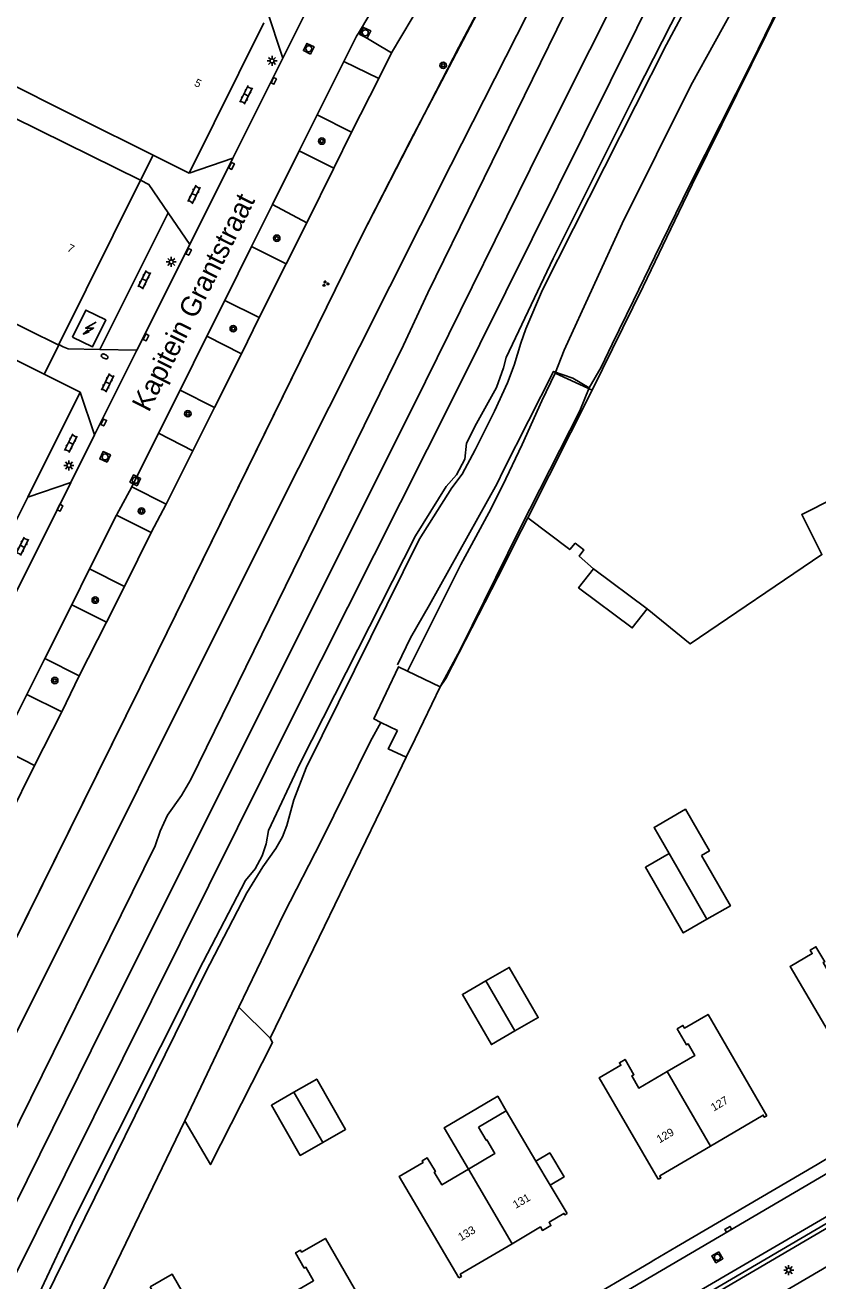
# Model space of a CAD drawing. Extents: x 135999 to 138000, y 396000 to 398501.
# Drawn here: x 136118.4 to 136217.5, y 397514.6 to 397671.5 of the extents above; entities that cross this region are included whole.
import ezdxf

# ---------------------------------------------------------------- set-up
doc = ezdxf.new("R2010")
doc.units = 0
for name, color, linetype in [('gg-afsc-hekwerk', 7, 'Continuous'), ('gg-afsc-muur', 7, 'Continuous'), ('gg-anno-huisnummerreeks BGT', 7, 'Continuous'), ('gg-anno-openbare ruimte label', 7, 'Continuous'), ('gg-aspt-spoorlijn', 7, 'Continuous'), ('gg-bbg-bijgebouw', 7, 'Continuous'), ('gg-bbg-gedigitaliseerde bebouwing', 7, 'Continuous'), ('gg-bbg-gedigitaliseerde bijgebouw', 7, 'Continuous'), ('gg-bbg-hoofdgebouw', 7, 'Continuous'), ('gg-bbg-luifel en loopbrug', 7, 'Continuous'), ('gg-bbg-overig bouwwerk', 7, 'Continuous'), ('gg-bbg-tussenscheiding', 7, 'Continuous'), ('gg-knt-verharding', 7, 'Continuous'), ('gg-knt-verharding nz', 7, 'Continuous'), ('gt-grn-bladgrens', 7, 'Continuous'), ('gt-grn-groengrens', 7, 'Continuous'), ('gt-grn-vlakafsluiter', 7, 'Continuous'), ('gt-grn-weggrens', 7, 'Continuous'), ('gt-symb-boom', 7, 'Continuous'), ('gt-symb-brandkraan', 7, 'Continuous'), ('gt-symb-groenvak', 7, 'Continuous'), ('gt-symb-klinker verharding', 7, 'Continuous'), ('gt-symb-kolk', 7, 'Continuous'), ('gt-symb-kolk center center', 7, 'Continuous'), ('gt-symb-lichtmast', 7, 'Continuous'), ('gt-symb-rioolschacht', 7, 'Continuous'), ('gt-symb-trafo symbool', 7, 'Continuous'), ('gx-grn-maaiveld', 7, 'Continuous')]:
    doc.layers.add(name, color=color, linetype=linetype)

# ---------------------------------------------------------------- blocks, each defined once
blk = doc.blocks.new('gt0-BOOM')
at = {"layer": 'gt-symb-boom'}
for radius in [0.4, 0.2]:
    blk.add_circle((0, 0), radius, dxfattribs=at)
blk = doc.blocks.new('gt0-RS')
at = {"layer": 'gt-symb-rioolschacht'}
blk.add_lwpolyline([(-0.5, -0.5), (0.5, -0.5), (0.5, 0.5), (-0.5, 0.5)], close=True, dxfattribs=at)
blk.add_circle((0, 0), 0.375, dxfattribs=at)
blk = doc.blocks.new('gt0-GRVAK')
at = {"layer": 'gt-symb-groenvak'}
for p, q in [((-0.11, 0.19), (-0.23, 0.24)), ((-0.18, 0.15), (0.09, 0.15)), ((-0.09, 0.21), (-0.16, 0.32)), ((-0.05, 0.21), (-0.05, 0.39)), ((0, 0.21), (0.06, 0.32)), ((0.02, 0.19), (0.13, 0.24)), ((0.26, -0.05), (0.2, 0.06)), ((0.3, -0.05), (0.3, 0.13)), ((0.35, -0.05), (0.41, 0.06)), ((-0.24, -0.23), (-0.36, -0.18)), ((-0.32, -0.26), (-0.05, -0.26)), ((-0.23, -0.21), (-0.29, -0.1)), ((-0.18, -0.2), (-0.18, -0.02)), ((-0.14, -0.21), (-0.07, -0.1)), ((-0.12, -0.23), (0, -0.18)), ((0.24, -0.07), (0.12, -0.02)), ((0.17, -0.11), (0.44, -0.11)), ((0.37, -0.07), (0.49, -0.02))]:
    blk.add_line(p, q, dxfattribs=at)
blk = doc.blocks.new('gt0-LMAST')
at = {"layer": 'gt-symb-lichtmast'}
for p, q in [((-0.18, 0.17), (-0.45, 0.44)), ((-0.01, 0.25), (-0.01, 0.62)), ((0.17, 0.17), (0.44, 0.44)), ((-0.26, 0), (-0.63, 0)), ((-0.18, -0.18), (-0.45, -0.45)), ((-0.01, -0.25), (-0.01, -0.63)), ((0.44, -0.45), (0.17, -0.18)), ((0.24, 0), (0.62, 0))]:
    blk.add_line(p, q, dxfattribs=at)
blk.add_circle((-0.01, 0), 0.25, dxfattribs=at)
blk = doc.blocks.new('gt0-KOLKCC')
at = {"layer": 'gt-symb-kolk center center'}
blk.add_lwpolyline([(-0.38, 0.2), (0.38, 0.2), (0.38, -0.2), (-0.38, -0.2)], close=True, dxfattribs=at)
blk = doc.blocks.new('gt0-KL1')
at = {"layer": 'gt-symb-klinker verharding'}
for p, q in [((-1.15, 0.3), (1.15, 0.3)), ((-1, -0.3), (-1, 0.3)), ((-0.5, 0.3), (-0.5, 0.45)), ((0, -0.3), (0, 0.3)), ((0.5, 0.3), (0.5, 0.45)), ((1, -0.3), (1, 0.3)), ((-1.15, -0.3), (1.15, -0.3)), ((-0.5, -0.45), (-0.5, -0.3)), ((0.5, -0.45), (0.5, -0.3))]:
    blk.add_line(p, q, dxfattribs=at)
blk = doc.blocks.new('gt0-BR')
at = {"layer": 'gt-symb-brandkraan'}
for centre, radius, start, end in [((-0.24, 0), 0.206, 107.5669, 252.4331), ((0.6, -2.66), 3, 106.892, 107.5669), ((0, -0.69), 0.938, 73.108, 106.892), ((-0.6, -2.66), 3, 72.4331, 73.108), ((0.24, 0), 0.206, 287.567, 72.4331), ((0.6, 2.66), 3, 252.4331, 253.108), ((0, 0.69), 0.938, 253.108, 286.8921), ((-0.6, 2.66), 3, 286.8921, 287.567)]:
    blk.add_arc(centre, radius, start, end, dxfattribs=at)
blk = doc.blocks.new('gt0-HSP')
at = {"layer": 'gt-symb-trafo symbool'}
for points in [[(0.77, 0.75), (-0.53, 0), (0.47, 0), (-0.83, -0.75)], [(-0.22, -0.24), (-0.83, -0.75), (-0.08, -0.48)]]:
    blk.add_lwpolyline(points, dxfattribs=at)
blk = doc.blocks.new('gt0-KOLK')
at = {"layer": 'gt-symb-kolk'}
blk.add_lwpolyline([(0, 0), (0.38, 0), (0.38, 0.4), (-0.38, 0.4), (-0.38, 0), (0, 0)], dxfattribs=at)

msp = doc.modelspace()

# ---------------------------------------------------------------- linework, layer by layer
at = {"layer": 'gg-afsc-hekwerk'}
for points in [[(136206.22, 397710.07), (136203.26, 397711.27), (136196.98, 397710.23), (136193.86, 397709.75), (136188.71, 397699.53), (136178.32, 397679.53), (136172.59, 397668.77), (136160.48, 397645.24), (136132.77, 397588.81), (136102.14, 397526.87), (136090.23, 397502.97), (136088.59, 397499.81), (136086.91, 397496.59), (136075.23, 397472.87), (136076.15, 397472.41)], [(136214.71, 397678.23), (136211.7, 397672), (136209.11, 397666.71), (136201.46, 397651.57), (136197.09, 397642.6), (136194.4, 397637.1), (136191.77, 397631.66), (136190.36, 397628.79), (136188.87, 397626.19)], [(136164.95, 397591.58), (136166.54, 397594.96), (136168.91, 397599.09), (136177.38, 397614.23), (136178.18, 397615.9), (136184.44, 397628.25), (136186.83, 397627.39), (136188.87, 397626.19)], [(136170.26, 397588.86), (136172.76, 397593.46), (136180.21, 397608.58), (136187.72, 397623.34), (136188.87, 397626.19)]]:
    msp.add_lwpolyline(points, dxfattribs=at)
at = {"layer": 'gg-afsc-muur'}
for p, q in [((136217.35, 397529.16), (136199.77, 397518.9)), ((136217.35, 397529.16), (136199.77, 397518.9)), ((136196.49, 397516.94), (136196.94, 397517.22)), ((136196.49, 397516.94), (136196.94, 397517.22))]:
    msp.add_line(p, q, dxfattribs=at)
at = {"layer": 'gg-aspt-spoorlijn'}
for points in [[(136075.9, 397441.46), (136078.9, 397447.5), (136110.62, 397511), (136126.65, 397543.4), (136168.42, 397626.98), (136182.98, 397656.49), (136206.97, 397704.32), (136208.88, 397708.17)], [(136081.38, 397443.76), (136105.46, 397491.91), (136152.12, 397585.65), (136171.93, 397625.02), (136194.83, 397671.15), (136212.4, 397706.41)]]:
    msp.add_lwpolyline(points, dxfattribs=at)
at = {"layer": 'gg-bbg-bijgebouw'}
msp.add_lwpolyline([(136124.34, 397632.55), (136126.81, 397631.32), (136128.49, 397634.69), (136126.01, 397635.92), (136124.34, 397632.55)], dxfattribs=at)
at = {"layer": 'gg-bbg-gedigitaliseerde bebouwing'}
for p, q in [((136125.05, 397659.93), (136071.25, 397686.71)), ((136134.4, 397655.27), (136125.05, 397659.93)), ((136132.84, 397652.13), (136123.46, 397656.75)), ((136138.89, 397653.04), (136134.4, 397655.27)), ((136175.07, 397533.84), (136178.52, 397535.88)), ((136178.52, 397535.88), (136182.23, 397529.6)), ((136182.23, 397529.6), (136184.01, 397526.59)), ((136184.01, 397526.59), (136186.11, 397523.04))]:
    msp.add_line(p, q, dxfattribs=at)
for points in [[(136123.46, 397656.75), (136096.92, 397669.84), (136086.86, 397649.26), (136103.12, 397641.19)], [(136221.4, 397541.27), (136213.99, 397553.91), (136216.74, 397555.53), (136216.49, 397555.96), (136217.21, 397556.38), (136218.31, 397554.51), (136218.1, 397554.39), (136219.06, 397552.75), (136222.49, 397554.77)], [(136198.63, 397540.78), (136202.09, 397542.79), (136201.24, 397544.25), (136201.03, 397544.13), (136199.88, 397546.12), (136200.6, 397546.54), (136200.78, 397546.22), (136203.73, 397547.92), (136211.08, 397535.24)], [(136197.49, 397527.32), (136190.13, 397540), (136192.84, 397541.57), (136192.66, 397541.88), (136193.36, 397542.29), (136194.46, 397540.38), (136194.19, 397540.23), (136195.07, 397538.72), (136198.63, 397540.78)], [(136173.8, 397528.6), (136177.1, 397530.55), (136176.1, 397532.25), (136176.03, 397532.21), (136175.07, 397533.84)], [(136172.6, 397515.03), (136165.13, 397527.67), (136168.13, 397529.44), (136168.02, 397529.63), (136168.65, 397530), (136169.66, 397528.29), (136169.53, 397528.21), (136170.46, 397526.64), (136173.8, 397528.6)], [(136163.28, 397507.24), (136155.93, 397519.94), (136152.95, 397518.22), (136152.8, 397518.48), (136152.19, 397518.14), (136153.29, 397516.23), (136153.48, 397516.34), (136154.45, 397514.65), (136151.05, 397512.69)]]:
    msp.add_lwpolyline(points, dxfattribs=at)
at = {"layer": 'gg-bbg-gedigitaliseerde bijgebouw'}
for points in [[(136198.87, 397568.02), (136196.99, 397571.29), (136200.91, 397573.55), (136203.9, 397568.35), (136202.9, 397567.77)], [(136203.6, 397559.81), (136200.63, 397558.1), (136195.9, 397566.31), (136198.87, 397568.02)], [(136203.6, 397559.81), (136206.52, 397561.49), (136202.9, 397567.77)], [(136179.61, 397545.85), (136182.51, 397547.52), (136178.9, 397553.8), (136175.98, 397552.12)], [(136179.61, 397545.85), (136176.67, 397544.15), (136173.05, 397550.43), (136175.98, 397552.12)], [(136155.62, 397531.93), (136158.45, 397533.56), (136154.84, 397539.85), (136152, 397538.21)], [(136155.62, 397531.93), (136152.78, 397530.3), (136149.17, 397536.58), (136152, 397538.21)], [(136134.04, 397513.88), (136136.78, 397515.46), (136141.07, 397508.01), (136138.32, 397506.43), (136134.04, 397513.88)]]:
    msp.add_lwpolyline(points, dxfattribs=at)
at = {"layer": 'gg-bbg-hoofdgebouw'}
for p, q in [((136148.25, 397671.8), (136138.89, 397653.04)), ((136132.84, 397652.13), (136122.64, 397631.61)), ((136122.6, 397631.52), (136111.61, 397636.98)), ((136122.64, 397631.61), (136122.6, 397631.52)), ((136120.8, 397627.91), (136125.3, 397625.66)), ((136125.3, 397625.66), (136118.75, 397612.54)), ((136118.75, 397612.54), (136117.04, 397609.12))]:
    msp.add_line(p, q, dxfattribs=at)
for points in [[(136111.61, 397636.98), (136109.84, 397633.37), (136120.8, 397627.91)], [(136211.08, 397535.24), (136210.76, 397535.08), (136210.62, 397535.34), (136204.02, 397531.47)], [(136204.02, 397531.47), (136197.69, 397527.75), (136197.82, 397527.48), (136197.49, 397527.32)], [(136186.11, 397523.04), (136185.85, 397522.87), (136185.72, 397523.05), (136183.88, 397521.96), (136184.1, 397521.55), (136183.03, 397520.94), (136182.78, 397521.37), (136179.24, 397519.28)], [(136179.24, 397519.28), (136172.77, 397515.46), (136172.91, 397515.18), (136172.6, 397515.03)]]:
    msp.add_lwpolyline(points, dxfattribs=at)
at = {"layer": 'gg-bbg-luifel en loopbrug'}
for points in [[(136178.52, 397535.88), (136177.45, 397537.69), (136170.76, 397533.74), (136173.8, 397528.6)], [(136184.01, 397526.59), (136185.74, 397527.61), (136183.96, 397530.62), (136182.23, 397529.6)]]:
    msp.add_lwpolyline(points, dxfattribs=at)
at = {"layer": 'gg-bbg-overig bouwwerk'}
for p, q in [((136170.26, 397588.86), (136166.18, 397590.82)), ((136167.12, 397582.36), (136170.26, 397588.86)), ((136162.86, 397584.41), (136164.93, 397583.41)), ((136167.12, 397582.36), (136166.02, 397580.08))]:
    msp.add_line(p, q, dxfattribs=at)
for points in [[(136166.18, 397590.82), (136165.05, 397591.36), (136161.99, 397584.83), (136162.86, 397584.41)], [(136164.93, 397583.41), (136163.77, 397581.1), (136166.02, 397580.08)]]:
    msp.add_lwpolyline(points, dxfattribs=at)
at = {"layer": 'gg-bbg-tussenscheiding'}
for p, q in [((136203.6, 397559.81), (136198.87, 397568.02)), ((136175.98, 397552.12), (136179.61, 397545.85)), ((136198.63, 397540.78), (136204.02, 397531.47)), ((136155.62, 397531.93), (136152, 397538.21)), ((136173.8, 397528.6), (136179.24, 397519.28))]:
    msp.add_line(p, q, dxfattribs=at)
at = {"layer": 'gg-knt-verharding'}
for p, q in [((136168.07, 397674.54), (136164.19, 397668.06)), ((136164.19, 397668.06), (136160.04, 397670.53)), ((136158.22, 397666.99), (136162.58, 397664.84)), ((136162.58, 397664.84), (136159.2, 397658.15)), ((136154.88, 397660.29), (136152.65, 397655.81)), ((136159.2, 397658.15), (136154.88, 397660.29)), ((136152.65, 397655.81), (136156.98, 397653.63)), ((136156.98, 397653.63), (136153.62, 397646.8)), ((136149.31, 397649.09), (136146.7, 397643.85)), ((136153.62, 397646.8), (136149.31, 397649.09)), ((136146.7, 397643.85), (136151.01, 397641.68)), ((136151.01, 397641.68), (136147.66, 397634.97)), ((136143.35, 397637.12), (136141.13, 397632.65)), ((136147.66, 397634.97), (136143.35, 397637.12)), ((136141.13, 397632.65), (136145.45, 397630.47)), ((136145.45, 397630.47), (136142.07, 397623.76)), ((136137.76, 397625.9), (136135.07, 397620.52)), ((136142.07, 397623.76), (136137.76, 397625.9)), ((136135.07, 397620.52), (136139.37, 397618.35)), ((136139.37, 397618.35), (136136.02, 397611.68)), ((136131.72, 397613.84), (136129.84, 397610.29)), ((136136.02, 397611.68), (136131.72, 397613.84)), ((136129.84, 397610.29), (136134.17, 397608.11)), ((136134.17, 397608.11), (136130.81, 397601.39)), ((136126.47, 397603.57), (136124.23, 397599.11)), ((136130.81, 397601.39), (136126.47, 397603.57)), ((136124.23, 397599.11), (136128.56, 397596.94)), ((136128.56, 397596.94), (136125.18, 397590.22)), ((136120.88, 397592.38), (136118.62, 397587.91)), ((136125.18, 397590.22), (136120.88, 397592.38)), ((136118.62, 397587.91), (136122.98, 397585.73)), ((136122.98, 397585.73), (136119.6, 397579.01)), ((136119.6, 397579.01), (136115.28, 397581.23)), ((136220.15, 397530.82), (136217.35, 397529.16)), ((136196.94, 397517.22), (136199.77, 397518.9))]:
    msp.add_line(p, q, dxfattribs=at)
for points in [[(136160.04, 397670.53), (136159.79, 397670.12), (136158.22, 397666.99)], [(136154.43, 397490.43), (136206.35, 397520.89), (136227.04, 397533), (136240.35, 397540.82), (136259.46, 397552.07), (136276.59, 397562.11), (136287.32, 397568.41), (136289.03, 397569.4)], [(136289.47, 397564.17), (136255.15, 397544.03), (136190.06, 397506), (136159.32, 397487.99), (136158.49, 397487.49)], [(136161.34, 397482.9), (136241.87, 397530.06), (136295.03, 397560.71), (136295.87, 397561.3)], [(136196.49, 397516.94), (136168.4, 397500.43), (136153.05, 397491.42), (136148.38, 397488.72)]]:
    msp.add_lwpolyline(points, dxfattribs=at)
at = {"layer": 'gg-knt-verharding nz'}
for p, q in [((136160.76, 397687.7), (136150.62, 397667.4)), ((136163.89, 397676.99), (136160.04, 397670.53)), ((136150.62, 397667.4), (136148.56, 397673.57)), ((136150.62, 397667.4), (136144.36, 397654.88)), ((136158.22, 397666.99), (136154.88, 397660.29)), ((136152.65, 397655.81), (136149.31, 397649.09)), ((136138.89, 397653.04), (136144.36, 397654.88)), ((136144.36, 397654.88), (136138.97, 397644.1)), ((136138.97, 397644.1), (136136.28, 397648.06)), ((136138.97, 397644.1), (136132.38, 397630.92)), ((136146.7, 397643.85), (136143.35, 397637.12)), ((136141.13, 397632.65), (136137.76, 397625.9)), ((136132.38, 397630.92), (136127.07, 397620.31)), ((136132.38, 397630.92), (136127.75, 397631)), ((136125.3, 397625.66), (136127.07, 397620.31)), ((136135.07, 397620.52), (136131.72, 397613.84)), ((136127.07, 397620.31), (136124.11, 397614.38)), ((136124.11, 397614.38), (136115.17, 397596.49)), ((136124.11, 397614.38), (136118.75, 397612.54)), ((136129.84, 397610.29), (136126.47, 397603.57)), ((136124.23, 397599.11), (136120.88, 397592.38)), ((136118.62, 397587.91), (136115.28, 397581.23))]:
    msp.add_line(p, q, dxfattribs=at)
for points in [[(136136.28, 397648.06), (136133.87, 397651.62), (136132.84, 397652.13)], [(136127.75, 397631), (136123.78, 397631.07), (136123.18, 397631.34), (136122.64, 397631.61)]]:
    msp.add_lwpolyline(points, dxfattribs=at)
at = {"layer": 'gt-grn-bladgrens'}
for p, q in [((136165.68, 397631.54), (136168.74, 397638.06)), ((136139.1, 397577.27), (136165.68, 397631.54)), ((136137.93, 397575.26), (136139.1, 397577.27)), ((136136.18, 397572.83), (136137.93, 397575.26)), ((136135.3, 397570.81), (136136.18, 397572.83)), ((136134.66, 397568.99), (136135.3, 397570.81)), ((136110.12, 397519.26), (136134.66, 397568.99))]:
    msp.add_line(p, q, dxfattribs=at)
at = {"layer": 'gt-grn-groengrens'}
for p, q in [((136164.19, 397668.06), (136162.58, 397664.84)), ((136156.98, 397653.63), (136159.2, 397658.15)), ((136153.62, 397646.8), (136151.01, 397641.68)), ((136147.66, 397634.97), (136145.45, 397630.47)), ((136142.07, 397623.76), (136139.37, 397618.35)), ((136134.17, 397608.11), (136136.02, 397611.68)), ((136130.81, 397601.39), (136128.56, 397596.94)), ((136125.18, 397590.22), (136122.98, 397585.73)), ((136119.6, 397579.01), (136116.36, 397572.51))]:
    msp.add_line(p, q, dxfattribs=at)
for points in [[(136289.46, 397563.39), (136289.71, 397562.96), (136162.46, 397488.32), (136162.21, 397488.75)], [(136289.46, 397563.39), (136181.39, 397500), (136162.21, 397488.75)]]:
    msp.add_lwpolyline(points, dxfattribs=at)
at = {"layer": 'gt-grn-vlakafsluiter'}
msp.add_line((136127.75, 397631), (136136.28, 397648.06), dxfattribs=at)
msp.add_lwpolyline([(136178.88, 397680.61), (136166.53, 397657.01), (136160.48, 397645.24), (136147.38, 397618.57), (136132.77, 397588.81), (136103.22, 397529.06), (136086.99, 397496.75)], dxfattribs=at)
at = {"layer": 'gt-grn-weggrens'}
for p, q in [((136132.84, 397652.13), (136134.4, 397655.27)), ((136120.8, 397627.91), (136122.6, 397631.52))]:
    msp.add_line(p, q, dxfattribs=at)
at = {"layer": 'gx-grn-maaiveld'}
for p, q in [((136191.71, 397685.03), (136168.74, 397638.06)), ((136189.24, 397625.89), (136195.64, 397638.87)), ((136189.24, 397625.89), (136184.65, 397628.02)), ((136189.24, 397625.89), (136181.2, 397609.95)), ((136181.2, 397609.95), (136179.6, 397606.78)), ((136179.37, 397606.32), (136179.6, 397606.78)), ((136189.42, 397603.61), (136196.14, 397598.6)), ((136170.26, 397588.86), (136170.99, 397589.9)), ((136145.1, 397548.84), (136138.35, 397534.64)), ((136145.1, 397548.84), (136149.02, 397544.96)), ((136119.96, 397496.47), (136138.35, 397534.64))]:
    msp.add_line(p, q, dxfattribs=at)
for points in [[(136079.12, 397470.95), (136089.3, 397490.11), (136093.09, 397497.58), (136116.32, 397543.68), (136148.79, 397608.63), (136171.6, 397654), (136190.78, 397691.87), (136195.5, 397701), (136198.41, 397705.89), (136200.96, 397709.86), (136201.44, 397710.49), (136201.81, 397710.81)], [(136210.06, 397679.95), (136207.68, 397674.99), (136201.57, 397663.97), (136192.99, 397646.73), (136185.77, 397630.92), (136184.65, 397628.02)], [(136195.64, 397638.87), (136200.09, 397648.16), (136201.74, 397651.62), (136214.74, 397677.92)], [(136120.15, 397513.06), (136124.63, 397522.56), (136140.64, 397554.49), (136145.93, 397564.67), (136147.14, 397566.1), (136148.02, 397567.72), (136148.52, 397569.25), (136148.83, 397570.9), (136152.79, 397579.3), (136167.16, 397607.7), (136171.03, 397613.89), (136172.31, 397615.35), (136173.35, 397617.31), (136173.57, 397619.27), (136174.8, 397621.75), (136177.28, 397626.26), (136178.16, 397628.71), (136178.5, 397630), (136184.4, 397642.34), (136194.74, 397663.1), (136201.25, 397675.88)], [(136120.86, 397512.36), (136140.9, 397553.07), (136146.11, 397563.1), (136148.11, 397566.36), (136149.74, 397568.65), (136150.56, 397570.11), (136151.12, 397571.52), (136151.99, 397574.72), (136153.52, 397578.74), (136167.64, 397607.25), (136171.7, 397613.71), (136173.03, 397615.41), (136174.64, 397618.47), (136177.04, 397623.29), (136178.69, 397626.84), (136179.5, 397629.04), (136180.32, 397631.79), (136180.95, 397633.57), (136183.04, 397638.44), (136198.56, 397669.09), (136201.6, 397674.8)], [(136260.21, 397632.52), (136259.05, 397632.27), (136231.7, 397618.57), (136215.43, 397610.38), (136217.95, 397605.36), (136201.48, 397594.2), (136196.14, 397598.6)], [(136184.65, 397628.02), (136182.96, 397624.56), (136180.52, 397619.12), (136178.06, 397613.97), (136176.34, 397610.57), (136172.86, 397604.14), (136166.18, 397590.82)], [(136181.2, 397609.95), (136186.45, 397605.99), (136187.14, 397606.79), (136188.2, 397605.98), (136187.64, 397605.16), (136189.42, 397603.61)], [(136170.99, 397589.9), (136177.46, 397602.55), (136179.37, 397606.32)], [(136189.42, 397603.61), (136187.56, 397601.23), (136194.27, 397596.21), (136196.14, 397598.6)], [(136162.86, 397584.41), (136161.57, 397582.07), (136155.44, 397569.64), (136150.74, 397560.49), (136145.1, 397548.84)], [(136166.02, 397580.08), (136163.54, 397574.95), (136155.8, 397558.96), (136149.02, 397544.96)], [(136149.02, 397544.96), (136149.33, 397544.41), (136141.57, 397529.17), (136138.35, 397534.64)]]:
    msp.add_lwpolyline(points, dxfattribs=at)

# ---------------------------------------------------------------- block references
at = {"layer": 'gt-symb-boom'}
for p in [(136170.64, 397666.49), (136155.47, 397657.03), (136149.85, 397644.89), (136144.41, 397633.59), (136138.74, 397622.97), (136132.95, 397610.81), (136127.17, 397599.68), (136122.11, 397589.64)]:
    msp.add_blockref('gt0-BOOM', p, dxfattribs=at)
at = {"layer": 'gt-symb-brandkraan', "rotation": 153.58862510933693}
msp.add_blockref('gt0-BR', (136128.34, 397630.12), dxfattribs=at)
at = {"layer": 'gt-symb-groenvak'}
msp.add_blockref('gt0-GRVAK', (136155.93, 397639.22), dxfattribs=at)
at = {"layer": 'gt-symb-klinker verharding', "rotation": -116.23193993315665}
for p in [(136146.03, 397662.79), (136139.52, 397650.36), (136133.3, 397639.7), (136128.71, 397626.83), (136124.12, 397619.28), (136118.06, 397606.4)]:
    msp.add_blockref('gt0-KL1', p, dxfattribs=at)
at = {"layer": 'gt-symb-kolk', "rotation": 30.384237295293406}
msp.add_blockref('gt0-KOLK', (136206.35, 397520.89), dxfattribs=at)
at = {"layer": 'gt-symb-kolk center center'}
for p, rotation in [((136149.47, 397664.55), -114.89920052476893), ((136144.2, 397653.92), 63.38370037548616), ((136138.84, 397643.19), 63.63994179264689), ((136133.51, 397632.5), 63.332497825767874), ((136128.23, 397621.87), 63.51182146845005), ((136122.76, 397611.22), 63.76806006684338)]:
    msp.add_blockref('gt0-KOLKCC', p, dxfattribs=dict(at, rotation=rotation))
at = {"layer": 'gt-symb-lichtmast'}
for p in [(136149.27, 397667.05), (136136.67, 397641.94), (136123.89, 397616.51), (136213.81, 397515.97)]:
    msp.add_blockref('gt0-LMAST', p, dxfattribs=at)
at = {"layer": 'gt-symb-rioolschacht'}
for p, rotation in [((136160.91, 397670.56), 63.38370037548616), ((136153.85, 397668.57), 63.58862510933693), ((136128.4, 397617.57), 65.17685962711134), ((136132.17, 397614.65), 63.38370037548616), ((136204.9, 397517.58), -150.46121773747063)]:
    msp.add_blockref('gt0-RS', p, dxfattribs=dict(at, rotation=rotation))
at = {"layer": 'gt-symb-trafo symbool'}
msp.add_blockref('gt0-HSP', (136126.5, 397633.67), dxfattribs=at)

# ---------------------------------------------------------------- texts
at = {"layer": 'gg-anno-huisnummerreeks BGT'}
for s, rotation, p in [('5', 333.5, (136139.45, 397663.98)), ('7', 333.6, (136123.57, 397643.33)), ('127', 30.4, (136204.45, 397535.78)), ('129', 30.4, (136197.67, 397531.8)), ('131', 30.5, (136179.71, 397523.62)), ('133', 30.5, (136172.86, 397519.58))]:
    msp.add_text(s, height=1, rotation=rotation, dxfattribs=at).set_placement(p)
at = {"layer": 'gg-anno-openbare ruimte label'}
msp.add_text('Kapitein Grantstraat', height=2.5, rotation=63.4, dxfattribs=at).set_placement((136133.87, 397623.06))

doc.saveas('drawing.dxf')
